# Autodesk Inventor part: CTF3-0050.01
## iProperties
Shininess: 64.0
Length Units: 11269
Angle Units: 11279
Time Units: 11290
Mass Units: 11283
Length Display Precision: 3
Angle Display Precision: 2
Compacted: True
Part Number: CTF3-0050.01
Document SubType Name: Modeling
Created: 2003-11
Designer: Lollo
Density: 0.0
Volumn: 0.0
Area: 0.0
PropertySet Name: Model Information
Control State: 0
Master: False
Checked Out: False
Author: Lollo
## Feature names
1. Estrusione1 [Extrusion]
2. Estrusione2 [Extrusion]
3. Estrusione3 [Extrusion]
4. Estrusione4 [Extrusion]
5. Foro1 [Hole]
6. Estrusione7 [Extrusion]
7. Estrusione8 [Extrusion]
8. Smusso1 [Chamfer]
9. Estrusione10 [Extrusion]
10. Specchio1 [Mirror]
11. Specchio2 [Mirror]
12. Estrusione11 [Extrusion]
13. Estrusione12 [Extrusion]
14. Foro2 [Hole]
15. Smusso3 [Chamfer]
16. Smusso4 [Chamfer]
